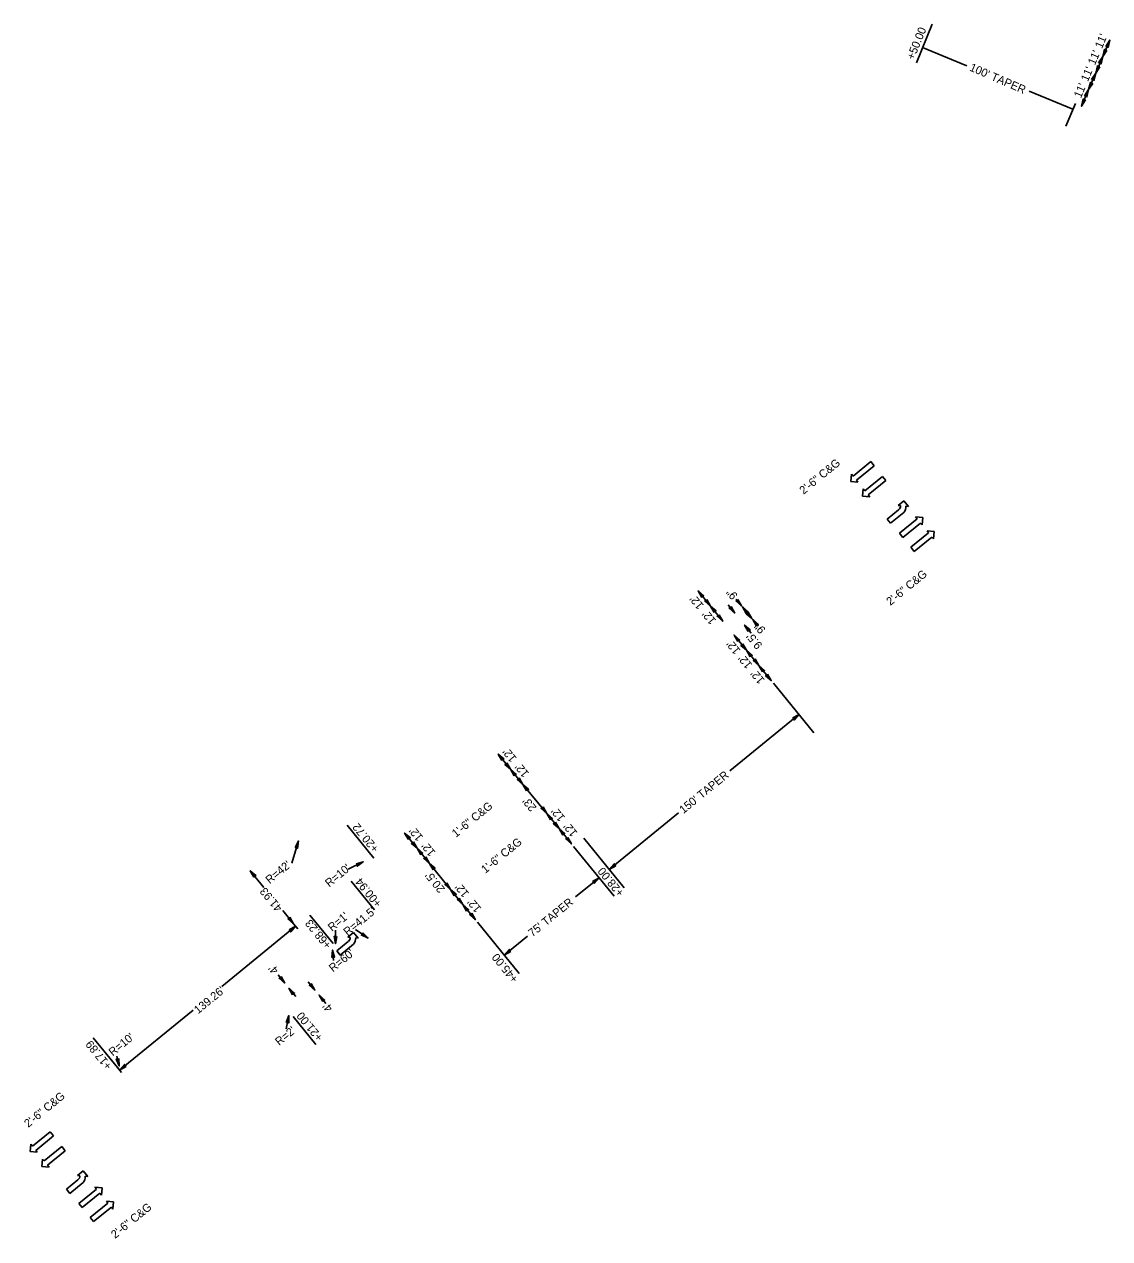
# Model space of a CAD drawing. Extents: x 2320991 to 2332664, y 598057 to 612602.
# Drawn here: x 2325713 to 2326378, y 601293 to 602037 of the extents above; entities that cross this region are included whole.
import ezdxf

# ---------------------------------------------------------------- set-up
doc = ezdxf.new("R2010")
doc.units = 0
for name, color, linetype in [('Prop Dimension', 7, 'Continuous'), ('Prop Dimension Text', 7, 'Continuous'), ('Prop Lane Arrow CELL', 7, 'Continuous'), ('Prop Terminator CELL', 7, 'Continuous')]:
    doc.layers.add(name, color=color, linetype=linetype)

msp = doc.modelspace()

# ---------------------------------------------------------------- linework, layer by layer
at = {"layer": 'Prop Dimension'}
for p, q in [((2326269.58, 602036.65), (2326259.94, 602013.11)), ((2326378.42, 602026.97), (2326374.11, 602016.85)), ((2326290.94, 602011.21), (2326263.73, 602022.36)), ((2326374.11, 602016.85), (2326369.81, 602006.73)), ((2326369.81, 602006.73), (2326365.5, 601996.6)), ((2326355.9, 601984.6), (2326329.02, 601995.61)), ((2326365.5, 601996.6), (2326361.2, 601986.48)), ((2326357.38, 601988.1), (2326351.49, 601974.23)), ((2326126.17, 601689.58), (2326133.76, 601680.29)), ((2326144.56, 601681.04), (2326148.67, 601676)), ((2326149.53, 601684.44), (2326152.85, 601680.38)), ((2326133.76, 601680.29), (2326141.35, 601670.99)), ((2326153.32, 601679.8), (2326156.63, 601675.74)), ((2326155.89, 601676.65), (2326159.2, 601672.59)), ((2326154.68, 601668.64), (2326158.79, 601663.61)), ((2326159.68, 601672.01), (2326162.99, 601667.96)), ((2326148.3, 601662.47), (2326155.89, 601653.17)), ((2326155.89, 601653.17), (2326163.48, 601643.88)), ((2326163.48, 601643.88), (2326171.07, 601634.58)), ((2326172.36, 601633.05), (2326197.2, 601602.62)), ((2326145.67, 601579.28), (2326188.03, 601613.86)), ((2326003.73, 601589.61), (2326011.32, 601580.32)), ((2326011.32, 601580.32), (2326018.91, 601571.02)), ((2326033.45, 601553.21), (2326018.9, 601571.03)), ((2326033.45, 601553.21), (2326041.04, 601543.92)), ((2326071.81, 601518.98), (2326114.3, 601553.67)), ((2325927.61, 601525.87), (2325911.17, 601546)), ((2325946.42, 601541.22), (2325954.01, 601531.93)), ((2326041.04, 601543.92), (2326048.63, 601534.62)), ((2325881.43, 601536.42), (2325877.27, 601522.87)), ((2325954.01, 601531.93), (2325961.6, 601522.63)), ((2326049.89, 601533.07), (2326074.74, 601502.64)), ((2326056.14, 601538.17), (2326080.98, 601507.74)), ((2325851.85, 601518.14), (2325860.22, 601507.9)), ((2325921.07, 601523.61), (2325911.74, 601519.06)), ((2325974.56, 601506.75), (2325961.6, 601522.63)), ((2325927.94, 601494.19), (2325913.63, 601511.71)), ((2326065.56, 601513.88), (2326051.13, 601502.1)), ((2325974.56, 601506.75), (2325982.15, 601497.46)), ((2325982.15, 601497.46), (2325989.74, 601488.16)), ((2325871.76, 601493.75), (2325878.37, 601485.66)), ((2325902.6, 601473.5), (2325888.3, 601491.03)), ((2325834.44, 601447.22), (2325879.63, 601484.11)), ((2325878.37, 601485.66), (2325880.89, 601482.57)), ((2325903.95, 601473.43), (2325904.13, 601481.66)), ((2325916.29, 601482.17), (2325924.01, 601476.91)), ((2325991, 601486.61), (2326016.64, 601455.21)), ((2326021.76, 601478.11), (2326007.47, 601466.45)), ((2325902.23, 601469.58), (2325902.8, 601463.13)), ((2325868.85, 601454.34), (2325872.96, 601449.3)), ((2325887.35, 601450.07), (2325891.46, 601445.04)), ((2325875.49, 601446.2), (2325879.69, 601441.07)), ((2325893.99, 601441.94), (2325898.18, 601436.8)), ((2325771.75, 601396.05), (2325816.81, 601432.83)), ((2325875.51, 601429.44), (2325873.77, 601421.26)), ((2325878.03, 601428.91), (2325892.04, 601411.76)), ((2325770.49, 601397.6), (2325755.61, 601415.82)), ((2325771.56, 601398.61), (2325770.08, 601404.64)), ((2325770.49, 601397.6), (2325773.02, 601394.5))]:
    msp.add_line(p, q, dxfattribs=at)
at = {"layer": 'Prop Lane Arrow CELL'}
for p, q in [((2326221.14, 601759.93), (2326232.01, 601768.75)), ((2326234.09, 601766.19), (2326223.22, 601757.37)), ((2326232.01, 601768.75), (2326234.09, 601766.19)), ((2326219.77, 601756.63), (2326220.2, 601761.09)), ((2326224.17, 601756.2), (2326219.77, 601756.63)), ((2326220.2, 601761.09), (2326221.14, 601759.93)), ((2326223.22, 601757.37), (2326224.17, 601756.2)), ((2326228.35, 601750.88), (2326239.22, 601759.7)), ((2326241.3, 601757.14), (2326230.43, 601748.32)), ((2326239.22, 601759.7), (2326241.3, 601757.14)), ((2326226.97, 601747.58), (2326227.4, 601752.05)), ((2326231.37, 601747.15), (2326226.97, 601747.58)), ((2326227.4, 601752.05), (2326228.35, 601750.88)), ((2326230.43, 601748.32), (2326231.37, 601747.15)), ((2326252.3, 601744.75), (2326248.78, 601741.95)), ((2326248.78, 601741.95), (2326250.26, 601741.8)), ((2326255.04, 601741.31), (2326252.3, 601744.75)), ((2326253.56, 601741.46), (2326255.04, 601741.31)), ((2326249.05, 601739.32), (2326241.96, 601733.54)), ((2326241.96, 601733.54), (2326244.05, 601730.98)), ((2326244.05, 601730.98), (2326252.22, 601737.65)), ((2326249.58, 601724.86), (2326260.45, 601733.68)), ((2326260.45, 601733.68), (2326259.5, 601734.85)), ((2326259.5, 601734.85), (2326263.9, 601734.43)), ((2326263.9, 601734.43), (2326263.47, 601729.96)), ((2326262.53, 601731.12), (2326251.66, 601722.3)), ((2326256.57, 601716.29), (2326267.44, 601725.11)), ((2326263.47, 601729.96), (2326262.53, 601731.12)), ((2326267.44, 601725.11), (2326266.5, 601726.28)), ((2326266.5, 601726.28), (2326270.9, 601725.86)), ((2326270.9, 601725.86), (2326270.47, 601721.39)), ((2326251.66, 601722.3), (2326249.58, 601724.86)), ((2326269.52, 601722.55), (2326258.65, 601713.73)), ((2326270.47, 601721.39), (2326269.52, 601722.55)), ((2326258.65, 601713.73), (2326256.57, 601716.29)), ((2325915.14, 601480.27), (2325911.62, 601477.47)), ((2325917.88, 601476.83), (2325915.14, 601480.27)), ((2325911.89, 601474.84), (2325904.8, 601469.06)), ((2325906.89, 601466.5), (2325915.06, 601473.17)), ((2325911.62, 601477.47), (2325913.1, 601477.32)), ((2325916.4, 601476.98), (2325917.88, 601476.83)), ((2325904.8, 601469.06), (2325906.89, 601466.5)), ((2325718.32, 601349.43), (2325729.19, 601358.25)), ((2325731.27, 601355.69), (2325720.39, 601346.86)), ((2325729.19, 601358.25), (2325731.27, 601355.69)), ((2325716.94, 601346.12), (2325717.37, 601350.59)), ((2325721.34, 601345.7), (2325716.94, 601346.12)), ((2325717.37, 601350.59), (2325718.32, 601349.43)), ((2325720.39, 601346.86), (2325721.34, 601345.7)), ((2325725.52, 601340.38), (2325736.39, 601349.2)), ((2325738.47, 601346.64), (2325727.6, 601337.81)), ((2325736.39, 601349.2), (2325738.47, 601346.64)), ((2325724.15, 601337.07), (2325724.58, 601341.54)), ((2325724.58, 601341.54), (2325725.52, 601340.38)), ((2325728.55, 601336.65), (2325724.15, 601337.07)), ((2325727.6, 601337.81), (2325728.55, 601336.65)), ((2325749.47, 601334.25), (2325745.95, 601331.44)), ((2325745.95, 601331.44), (2325747.43, 601331.29)), ((2325752.21, 601330.81), (2325749.47, 601334.25)), ((2325750.74, 601330.96), (2325752.21, 601330.81)), ((2325746.22, 601328.82), (2325739.13, 601323.03)), ((2325741.22, 601320.48), (2325749.39, 601327.15)), ((2325757.62, 601323.18), (2325756.68, 601324.35)), ((2325756.68, 601324.35), (2325761.08, 601323.92)), ((2325761.08, 601323.92), (2325760.65, 601319.45)), ((2325739.13, 601323.03), (2325741.22, 601320.48)), ((2325746.75, 601314.36), (2325757.62, 601323.18)), ((2325759.7, 601320.62), (2325748.83, 601311.8)), ((2325760.65, 601319.45), (2325759.7, 601320.62)), ((2325748.83, 601311.8), (2325746.75, 601314.36)), ((2325753.75, 601305.79), (2325764.62, 601314.61)), ((2325766.7, 601312.05), (2325755.83, 601303.23)), ((2325764.62, 601314.61), (2325763.67, 601315.77)), ((2325763.67, 601315.77), (2325768.07, 601315.35)), ((2325767.64, 601310.88), (2325766.7, 601312.05)), ((2325768.07, 601315.35), (2325767.64, 601310.88)), ((2325755.83, 601303.23), (2325753.75, 601305.79))]:
    msp.add_line(p, q, dxfattribs=at)
for centre, radius, start, end in [((2326247, 601741.85), 3.27, 309.22799, 358.88617), ((2326248.33, 601741.16), 5.25, 317.90406, 3.21576), ((2325909.84, 601477.38), 3.27, 309.22799, 358.88617), ((2325911.17, 601476.68), 5.25, 317.90406, 3.21576), ((2325744.17, 601331.35), 3.27, 309.22799, 358.88617), ((2325745.51, 601330.66), 5.25, 317.90406, 3.21576)]:
    msp.add_arc(centre, radius, start, end, dxfattribs=at)
at = {"layer": 'Prop Terminator CELL'}
for points in [[(2326375.94, 602023.14), (2326378.42, 602026.97), (2326377.38, 602022.5), (2326376.87, 602023.34)], [(2326371.64, 602013.01), (2326374.11, 602016.85), (2326373.08, 602012.37), (2326372.57, 602013.22)], [(2326376.59, 602020.69), (2326374.11, 602016.85), (2326375.15, 602021.33), (2326375.66, 602020.49)], [(2326372.28, 602010.57), (2326369.81, 602006.73), (2326370.84, 602011.2), (2326371.35, 602010.36)], [(2326367.98, 602000.44), (2326365.5, 601996.6), (2326366.54, 602001.08), (2326367.05, 602000.24)], [(2326367.33, 602002.89), (2326369.81, 602006.73), (2326368.77, 602002.25), (2326368.26, 602003.09)], [(2326363.03, 601992.77), (2326365.5, 601996.6), (2326364.47, 601992.13), (2326363.96, 601992.97)], [(2326363.67, 601990.32), (2326361.2, 601986.48), (2326362.23, 601990.96), (2326362.74, 601990.12)], [(2326128.42, 601685.61), (2326126.17, 601689.58), (2326129.65, 601686.58), (2326128.67, 601686.52)], [(2326131.51, 601684.26), (2326133.76, 601680.29), (2326130.28, 601683.29), (2326131.26, 601683.35)], [(2326150.6, 601684.36), (2326152.85, 601680.38), (2326149.36, 601683.38), (2326150.35, 601683.44)], [(2326136, 601676.31), (2326133.76, 601680.29), (2326137.24, 601677.29), (2326136.26, 601677.23)], [(2326139.1, 601674.97), (2326141.35, 601670.99), (2326137.87, 601673.99), (2326138.85, 601674.05)], [(2326146.42, 601679.98), (2326148.67, 601676), (2326145.19, 601679), (2326146.17, 601679.06)], [(2326155.57, 601675.82), (2326153.32, 601679.8), (2326156.8, 601676.8), (2326155.82, 601676.74)], [(2326156.96, 601676.57), (2326159.2, 601672.59), (2326155.72, 601675.59), (2326156.71, 601675.65)], [(2326156.92, 601664.67), (2326154.68, 601668.64), (2326158.16, 601665.64), (2326157.18, 601665.58)], [(2326161.92, 601668.04), (2326159.68, 601672.01), (2326163.16, 601669.01), (2326162.18, 601668.95)], [(2326150.55, 601658.49), (2326148.3, 601662.47), (2326151.78, 601659.47), (2326150.8, 601659.41)], [(2326153.65, 601657.15), (2326155.89, 601653.17), (2326152.41, 601656.17), (2326153.39, 601656.23)], [(2326158.14, 601649.2), (2326155.89, 601653.17), (2326159.37, 601650.18), (2326158.39, 601650.11)], [(2326161.23, 601647.86), (2326163.48, 601643.88), (2326160, 601646.88), (2326160.98, 601646.94)], [(2326165.73, 601639.9), (2326163.48, 601643.88), (2326166.96, 601640.88), (2326165.98, 601640.82)], [(2326168.82, 601638.56), (2326171.07, 601634.58), (2326167.59, 601637.58), (2326168.57, 601637.64)], [(2326184.05, 601611.61), (2326188.03, 601613.86), (2326185.03, 601610.38), (2326184.97, 601611.36)], [(2326005.98, 601585.64), (2326003.73, 601589.61), (2326007.21, 601586.61), (2326006.23, 601586.55)], [(2326009.08, 601584.29), (2326011.32, 601580.32), (2326007.84, 601583.32), (2326008.82, 601583.38)], [(2326013.57, 601576.34), (2326011.32, 601580.32), (2326014.8, 601577.32), (2326013.82, 601577.26)], [(2326016.67, 601575), (2326018.91, 601571.02), (2326015.43, 601574.02), (2326016.41, 601574.08)], [(2326021.15, 601567.06), (2326018.9, 601571.03), (2326022.39, 601568.03), (2326021.4, 601567.97)], [(2326031.2, 601557.19), (2326033.45, 601553.21), (2326029.97, 601556.21), (2326030.95, 601556.27)], [(2326035.7, 601549.24), (2326033.45, 601553.21), (2326036.93, 601550.22), (2326035.95, 601550.15)], [(2326038.79, 601547.89), (2326041.04, 601543.92), (2326037.56, 601546.92), (2326038.54, 601546.98)], [(2325948.67, 601537.25), (2325946.42, 601541.22), (2325949.9, 601538.22), (2325948.92, 601538.16)], [(2326043.28, 601539.94), (2326041.04, 601543.92), (2326044.52, 601540.92), (2326043.54, 601540.86)], [(2325879.36, 601532.34), (2325881.43, 601536.42), (2325880.86, 601531.86), (2325880.27, 601532.64)], [(2325951.76, 601535.9), (2325954.01, 601531.93), (2325950.53, 601534.93), (2325951.51, 601534.99)], [(2325956.25, 601527.95), (2325954.01, 601531.93), (2325957.49, 601528.93), (2325956.51, 601528.87)], [(2326046.38, 601538.6), (2326048.63, 601534.62), (2326045.15, 601537.62), (2326046.13, 601537.68)], [(2325959.35, 601526.61), (2325961.6, 601522.63), (2325958.12, 601525.63), (2325959.1, 601525.69)], [(2325854.09, 601514.17), (2325851.85, 601518.14), (2325855.33, 601515.15), (2325854.35, 601515.08)], [(2325916.69, 601522.34), (2325921.07, 601523.61), (2325917.36, 601520.91), (2325917.52, 601521.88)], [(2325963.84, 601518.66), (2325961.6, 601522.63), (2325965.08, 601519.63), (2325964.1, 601519.57)], [(2326075.78, 601521.22), (2326071.81, 601518.98), (2326074.81, 601522.46), (2326074.87, 601521.48)], [(2325972.32, 601510.73), (2325974.56, 601506.75), (2325971.08, 601509.75), (2325972.06, 601509.81)], [(2326061.59, 601511.63), (2326065.56, 601513.88), (2326062.56, 601510.4), (2326062.5, 601511.38)], [(2325976.81, 601502.78), (2325974.56, 601506.75), (2325978.04, 601503.75), (2325977.06, 601503.69)], [(2325979.91, 601501.43), (2325982.15, 601497.46), (2325978.67, 601500.46), (2325979.65, 601500.52)], [(2325984.4, 601493.48), (2325982.15, 601497.46), (2325985.63, 601494.46), (2325984.65, 601494.4)], [(2325876.12, 601489.64), (2325878.37, 601485.66), (2325874.88, 601488.66), (2325875.87, 601488.72)], [(2325987.49, 601492.14), (2325989.74, 601488.16), (2325986.26, 601491.16), (2325987.24, 601491.22)], [(2325875.65, 601481.87), (2325879.63, 601484.11), (2325876.63, 601480.63), (2325876.57, 601481.62)], [(2325920.73, 601480.09), (2325924.01, 601476.91), (2325919.82, 601478.8), (2325920.74, 601479.14)], [(2325904.82, 601477.91), (2325903.95, 601473.43), (2325903.25, 601477.97), (2325904.04, 601477.38)], [(2325901.86, 601465.03), (2325902.23, 601469.58), (2325903.43, 601465.14), (2325902.58, 601465.64)], [(2326011.44, 601468.69), (2326007.47, 601466.45), (2326010.46, 601469.93), (2326010.53, 601468.95)], [(2325870.72, 601453.28), (2325872.96, 601449.3), (2325869.48, 601452.3), (2325870.46, 601452.36)], [(2325877.74, 601442.23), (2325875.49, 601446.2), (2325878.97, 601443.21), (2325877.99, 601443.14)], [(2325889.21, 601449.01), (2325891.46, 601445.04), (2325887.98, 601448.04), (2325888.96, 601448.1)], [(2325896.23, 601437.96), (2325893.99, 601441.94), (2325897.47, 601438.94), (2325896.49, 601438.88)], [(2325873.82, 601425.2), (2325875.51, 601429.44), (2325875.35, 601424.84), (2325874.69, 601425.57)], [(2325771.24, 601403.17), (2325771.56, 601398.61), (2325769.7, 601402.81), (2325770.62, 601402.45)], [(2325775.73, 601398.29), (2325771.75, 601396.05), (2325774.75, 601399.53), (2325774.81, 601398.54)]]:
    msp.add_lwpolyline(points, close=True, dxfattribs=at)

# ---------------------------------------------------------------- texts
at = {"layer": 'Prop Dimension'}
for s, rotation, p in [('+50.00', 67.72044, (2326258.37, 602014.49)), ('+20.72', 129.22799, (2325930.91, 601531.84)), ('+28.00', 129.22799, (2326081.18, 601504.8)), ('+00.94', 129.22799, (2325932.66, 601498.24)), ('+68.23', 129.22799, (2325901.89, 601472.84)), ('+45.00', 129.22799, (2326016.33, 601452.06)), ('+21.00', 129.22799, (2325896.68, 601416.19)), ('+17.89', 129.22799, (2325767.4, 601398.76))]:
    msp.add_text(s, height=5, rotation=rotation, dxfattribs=at).set_placement(p)
at = {"layer": 'Prop Dimension Text'}
for s, rotation, p in [("11'", 66.96213, (2326373.65, 602021.43)), ("11'", 66.96213, (2326369.34, 602011.31)), ("100' TAPER", 336.58964, (2326292.11, 602008.44)), ("11'", 66.96213, (2326365.04, 602001.19)), ("11'", 66.96213, (2326360.74, 601991.07)), ('2\'-6" C&G', 39.22799, (2326190.84, 601748.42)), ('2\'-6" C&G', 39.22799, (2326244.03, 601680.36)), ('9"', 129.22799, (2326150.79, 601686.79)), ("12'", 129.22799, (2326129.98, 601680.73)), ("12'", 129.22799, (2326137.57, 601671.44)), ('9"', 129.22799, (2326167.87, 601665.87)), ("12'", 129.22799, (2326152.48, 601653.17)), ("9.5'", 129.22799, (2326165.9, 601656.38)), ("12'", 129.22799, (2326159.7, 601644.32)), ("12'", 129.22799, (2326167.29, 601635.03)), ("12'", 129.22799, (2326015.34, 601587.12)), ("12'", 129.22799, (2326022.93, 601577.83)), ("150' TAPER", 39.22799, (2326117.21, 601552.82)), ("23'", 129.22799, (2326027.52, 601556.94)), ('1\'-6" C&G', 39.22799, (2325977.84, 601538.27)), ("12'", 129.22799, (2326045.05, 601550.73)), ("12'", 129.22799, (2326052.64, 601541.43)), ("12'", 129.22799, (2325958.02, 601538.74)), ("12'", 129.22799, (2325965.61, 601529.44)), ('1\'-6" C&G', 39.22799, (2325995.83, 601516.24)), ("R=42'", 39.22799, (2325863.69, 601509.83)), ("R=10'", 39.22799, (2325900.19, 601507.83)), ("20.5'", 129.22799, (2325971.41, 601507.08)), ("12'", 129.22799, (2325986.17, 601504.26)), ('41.93', 129.58662, (2325871.74, 601495.52)), ("R=41.5'", 39.22799, (2325911.43, 601477.98)), ("12'", 129.22799, (2325993.76, 601494.97)), ("75' TAPER", 39.22799, (2326024.72, 601477.31)), ("R=1'", 39.22799, (2325901.89, 601480.7)), ("R=60'", 39.22799, (2325902.51, 601455.79)), ("4'", 129.22799, (2325869.53, 601457.28)), ("139.26'", 39.22799, (2325819.85, 601430.16)), ("4'", 129.22799, (2325902.72, 601434.1)), ("R=2'", 39.22799, (2325869.54, 601410.75)), ("R=10'", 39.22799, (2325767.58, 601404.31)), ('2\'-6" C&G', 39.22799, (2325715.78, 601360.59)), ('2\'-6" C&G', 39.22799, (2325768.98, 601292.53))]:
    msp.add_text(s, height=5, rotation=rotation, dxfattribs=at).set_placement(p)

doc.saveas('drawing.dxf')
